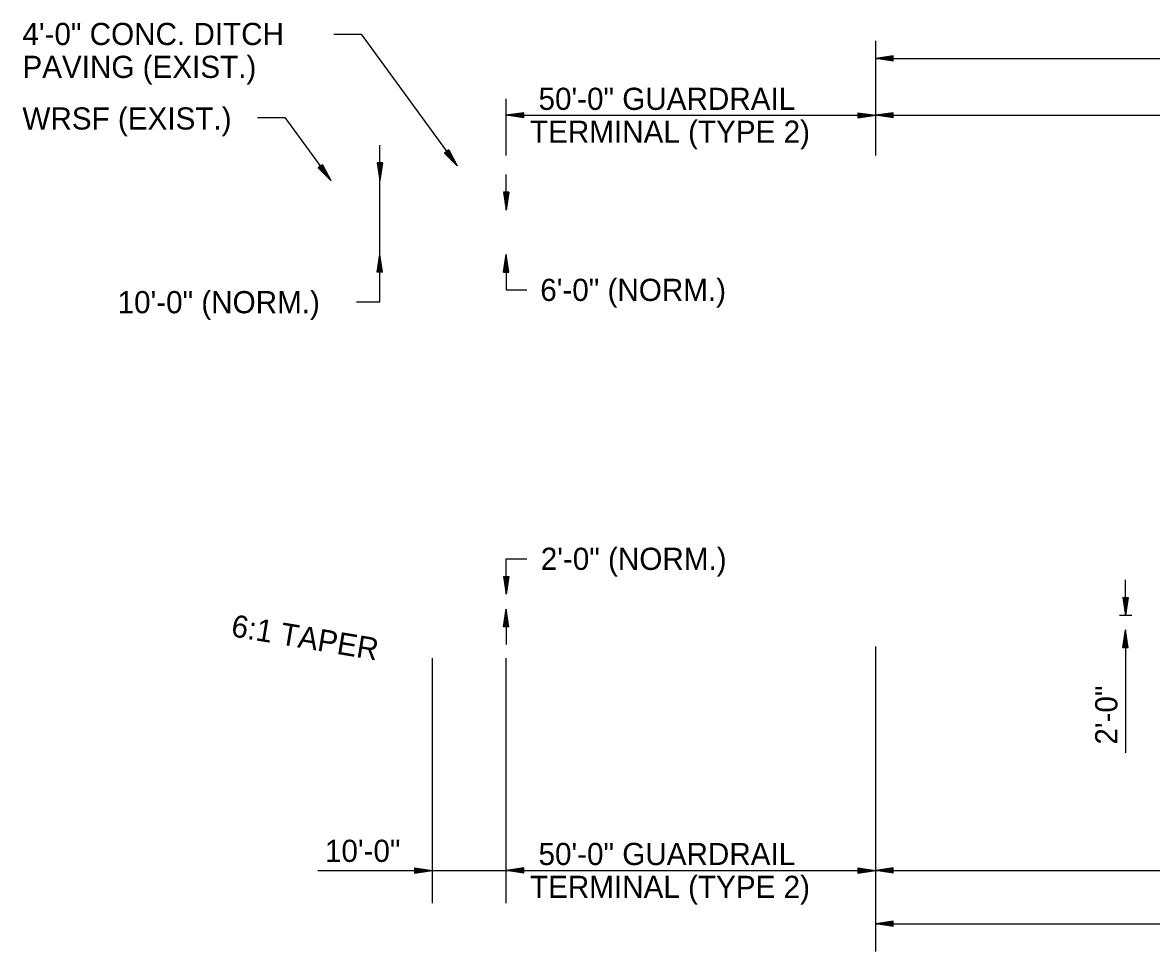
# Model space of a CAD drawing. Extents: x 1373853 to 1374003, y 380191 to 380927.
# Drawn here: x 1373853.14 to 1373883.7, y 380209.17 to 380234.32 of the extents above; entities that cross this region are included whole.
import ezdxf

# ---------------------------------------------------------------- set-up
doc = ezdxf.new("R2010")
doc.units = 0
doc.layers.add('2', color=7, linetype='Continuous')
doc.layers.add('7', color=7, linetype='Continuous')

msp = doc.modelspace()

# ---------------------------------------------------------------- linework, layer by layer
at = {"layer": '2'}
for p, q in [((1373876.236, 380230.714), (1373876.236, 380233.821)), ((1373876.236, 380233.341), (1373916.236, 380233.341)), ((1373866.236, 380230.714), (1373866.236, 380232.252)), ((1373866.236, 380231.806), (1373876.236, 380231.806)), ((1373876.236, 380231.806), (1373916.236, 380231.806)), ((1373862.817, 380230.041), (1373862.817, 380230.997)), ((1373866.236, 380229.241), (1373866.236, 380230.201)), ((1373862.817, 380228.041), (1373862.817, 380230.041)), ((1373862.817, 380226.748), (1373862.817, 380228.041)), ((1373862.817, 380226.748), (1373862.18, 380226.748)), ((1373882.998, 380218.276), (1373882.996, 380219.236)), ((1373866.236, 380218.441), (1373866.236, 380217.481)), ((1373882.831, 380218.276), (1373883.166, 380218.276)), ((1373882.998, 380217.876), (1373882.998, 380214.551)), ((1373876.236, 380209.174), (1373876.236, 380217.429)), ((1373864.236, 380210.478), (1373864.236, 380217.114)), ((1373866.236, 380210.478), (1373866.236, 380217.114)), ((1373861.131, 380211.366), (1373864.236, 380211.366)), ((1373864.236, 380211.366), (1373866.236, 380211.366)), ((1373866.236, 380211.366), (1373876.236, 380211.366)), ((1373876.236, 380211.366), (1373916.236, 380211.366)), ((1373876.236, 380209.921), (1373916.236, 380209.921))]:
    msp.add_line(p, q, dxfattribs=at)
for points in [[(1373861.572, 380234.001), (1373862.31, 380234.001), (1373864.903, 380230.441)], [(1373859.505, 380231.744), (1373860.243, 380231.744), (1373861.483, 380230.041)], [(1373866.236, 380228.041), (1373866.233, 380227.081), (1373866.792, 380227.081)], [(1373866.236, 380218.841), (1373866.233, 380219.801), (1373866.792, 380219.801)]]:
    msp.add_lwpolyline(points, dxfattribs=at)
at = {"layer": '7'}
for p, q in [((1373876.713, 380233.412), (1373876.236, 380233.341)), ((1373876.713, 380233.269), (1373876.713, 380233.412)), ((1373876.713, 380233.269), (1373876.236, 380233.341)), ((1373876.713, 380233.4), (1373876.315, 380233.341)), ((1373876.713, 380233.281), (1373876.315, 380233.341)), ((1373876.713, 380233.388), (1373876.398, 380233.341)), ((1373876.713, 380233.293), (1373876.398, 380233.341)), ((1373876.713, 380233.376), (1373876.479, 380233.341)), ((1373876.713, 380233.305), (1373876.479, 380233.341)), ((1373876.713, 380233.364), (1373876.558, 380233.341)), ((1373876.713, 380233.317), (1373876.558, 380233.341)), ((1373876.713, 380233.35), (1373876.639, 380233.341)), ((1373876.713, 380233.329), (1373876.639, 380233.341)), ((1373866.713, 380231.877), (1373866.236, 380231.806)), ((1373866.713, 380231.734), (1373866.713, 380231.877)), ((1373875.756, 380231.877), (1373876.236, 380231.806)), ((1373875.756, 380231.877), (1373875.756, 380231.734)), ((1373876.713, 380231.877), (1373876.236, 380231.806)), ((1373876.713, 380231.734), (1373876.713, 380231.877)), ((1373866.713, 380231.734), (1373866.236, 380231.806)), ((1373866.713, 380231.865), (1373866.315, 380231.806)), ((1373866.713, 380231.746), (1373866.315, 380231.806)), ((1373866.713, 380231.853), (1373866.398, 380231.806)), ((1373866.713, 380231.758), (1373866.398, 380231.806)), ((1373866.713, 380231.841), (1373866.479, 380231.806)), ((1373866.713, 380231.77), (1373866.479, 380231.806)), ((1373866.713, 380231.829), (1373866.558, 380231.806)), ((1373866.713, 380231.782), (1373866.558, 380231.806)), ((1373866.713, 380231.815), (1373866.639, 380231.806)), ((1373866.713, 380231.794), (1373866.639, 380231.806)), ((1373875.756, 380231.865), (1373876.155, 380231.806)), ((1373875.756, 380231.853), (1373876.071, 380231.806)), ((1373875.756, 380231.841), (1373875.992, 380231.806)), ((1373875.756, 380231.829), (1373875.913, 380231.806)), ((1373875.756, 380231.818), (1373875.832, 380231.806)), ((1373875.756, 380231.734), (1373876.236, 380231.806)), ((1373875.756, 380231.782), (1373875.913, 380231.806)), ((1373875.756, 380231.758), (1373876.071, 380231.806)), ((1373875.756, 380231.746), (1373876.155, 380231.806)), ((1373875.756, 380231.77), (1373875.992, 380231.806)), ((1373875.756, 380231.794), (1373875.832, 380231.806)), ((1373876.713, 380231.734), (1373876.236, 380231.806)), ((1373876.713, 380231.865), (1373876.315, 380231.806)), ((1373876.713, 380231.746), (1373876.315, 380231.806)), ((1373876.713, 380231.853), (1373876.398, 380231.806)), ((1373876.713, 380231.758), (1373876.398, 380231.806)), ((1373876.713, 380231.841), (1373876.479, 380231.806)), ((1373876.713, 380231.77), (1373876.479, 380231.806)), ((1373876.713, 380231.829), (1373876.558, 380231.806)), ((1373876.713, 380231.782), (1373876.558, 380231.806)), ((1373876.713, 380231.815), (1373876.639, 380231.806)), ((1373876.713, 380231.794), (1373876.639, 380231.806)), ((1373864.68, 380230.869), (1373864.564, 380230.785)), ((1373864.564, 380230.785), (1373864.903, 380230.441)), ((1373864.574, 380230.792), (1373864.857, 380230.505)), ((1373864.583, 380230.799), (1373864.808, 380230.572)), ((1373864.593, 380230.806), (1373864.76, 380230.638)), ((1373864.603, 380230.813), (1373864.713, 380230.702)), ((1373864.614, 380230.822), (1373864.666, 380230.767)), ((1373864.632, 380230.834), (1373864.666, 380230.767)), ((1373864.641, 380230.841), (1373864.713, 380230.702)), ((1373864.651, 380230.848), (1373864.76, 380230.638)), ((1373864.661, 380230.855), (1373864.808, 380230.572)), ((1373864.67, 380230.862), (1373864.857, 380230.505)), ((1373864.68, 380230.869), (1373864.903, 380230.441)), ((1373861.26, 380230.469), (1373861.144, 380230.385)), ((1373861.144, 380230.385), (1373861.483, 380230.041)), ((1373861.154, 380230.392), (1373861.437, 380230.105)), ((1373861.164, 380230.399), (1373861.388, 380230.172)), ((1373861.173, 380230.406), (1373861.34, 380230.238)), ((1373861.183, 380230.413), (1373861.294, 380230.302)), ((1373861.194, 380230.422), (1373861.246, 380230.367)), ((1373861.212, 380230.434), (1373861.246, 380230.367)), ((1373861.221, 380230.441), (1373861.294, 380230.302)), ((1373861.231, 380230.448), (1373861.34, 380230.238)), ((1373861.241, 380230.455), (1373861.388, 380230.172)), ((1373861.25, 380230.462), (1373861.437, 380230.105)), ((1373861.26, 380230.469), (1373861.483, 380230.041)), ((1373862.745, 380230.519), (1373862.817, 380230.041)), ((1373862.888, 380230.519), (1373862.745, 380230.519)), ((1373862.757, 380230.519), (1373862.817, 380230.12)), ((1373862.769, 380230.519), (1373862.817, 380230.204)), ((1373862.781, 380230.519), (1373862.817, 380230.285)), ((1373862.792, 380230.519), (1373862.817, 380230.364)), ((1373862.807, 380230.519), (1373862.816, 380230.445)), ((1373862.828, 380230.519), (1373862.816, 380230.445)), ((1373862.888, 380230.519), (1373862.817, 380230.041)), ((1373862.84, 380230.519), (1373862.817, 380230.364)), ((1373862.864, 380230.519), (1373862.817, 380230.204)), ((1373862.876, 380230.519), (1373862.817, 380230.12)), ((1373862.852, 380230.519), (1373862.817, 380230.285)), ((1373866.164, 380229.721), (1373866.236, 380229.241)), ((1373866.307, 380229.721), (1373866.164, 380229.721)), ((1373866.176, 380229.721), (1373866.236, 380229.322)), ((1373866.188, 380229.721), (1373866.236, 380229.404)), ((1373866.2, 380229.721), (1373866.236, 380229.485)), ((1373866.212, 380229.721), (1373866.236, 380229.566)), ((1373866.224, 380229.721), (1373866.236, 380229.645)), ((1373866.307, 380229.721), (1373866.236, 380229.241)), ((1373866.26, 380229.721), (1373866.236, 380229.566)), ((1373866.284, 380229.721), (1373866.236, 380229.404)), ((1373866.296, 380229.721), (1373866.236, 380229.322)), ((1373866.272, 380229.721), (1373866.236, 380229.485)), ((1373866.248, 380229.721), (1373866.236, 380229.645)), ((1373862.745, 380227.564), (1373862.817, 380228.041)), ((1373862.757, 380227.564), (1373862.817, 380227.962)), ((1373862.888, 380227.563), (1373862.817, 380228.041)), ((1373862.876, 380227.563), (1373862.817, 380227.962)), ((1373866.162, 380227.561), (1373866.236, 380228.041)), ((1373866.176, 380227.561), (1373866.236, 380227.96)), ((1373866.307, 380227.561), (1373866.236, 380228.041)), ((1373866.296, 380227.561), (1373866.236, 380227.96)), ((1373862.769, 380227.564), (1373862.817, 380227.879)), ((1373862.781, 380227.564), (1373862.817, 380227.798)), ((1373862.792, 380227.564), (1373862.817, 380227.719)), ((1373862.807, 380227.563), (1373862.816, 380227.638)), ((1373862.828, 380227.563), (1373862.816, 380227.638)), ((1373862.864, 380227.563), (1373862.817, 380227.879)), ((1373862.852, 380227.563), (1373862.817, 380227.798)), ((1373862.84, 380227.563), (1373862.817, 380227.719)), ((1373866.188, 380227.561), (1373866.236, 380227.879)), ((1373866.2, 380227.561), (1373866.236, 380227.798)), ((1373866.212, 380227.561), (1373866.236, 380227.719)), ((1373866.224, 380227.561), (1373866.236, 380227.638)), ((1373866.281, 380227.561), (1373866.236, 380227.879)), ((1373866.272, 380227.561), (1373866.236, 380227.798)), ((1373866.257, 380227.561), (1373866.236, 380227.719)), ((1373866.245, 380227.561), (1373866.236, 380227.638)), ((1373862.888, 380227.563), (1373862.745, 380227.564)), ((1373866.162, 380227.561), (1373866.307, 380227.561)), ((1373866.162, 380219.321), (1373866.236, 380218.841)), ((1373866.162, 380219.321), (1373866.307, 380219.321)), ((1373866.176, 380219.321), (1373866.236, 380218.922)), ((1373866.188, 380219.321), (1373866.236, 380219.004)), ((1373866.2, 380219.321), (1373866.236, 380219.085)), ((1373866.212, 380219.321), (1373866.236, 380219.164)), ((1373866.224, 380219.321), (1373866.236, 380219.245)), ((1373866.307, 380219.321), (1373866.236, 380218.841)), ((1373866.257, 380219.321), (1373866.236, 380219.164)), ((1373866.281, 380219.321), (1373866.236, 380219.004)), ((1373866.296, 380219.321), (1373866.236, 380218.922)), ((1373866.272, 380219.321), (1373866.236, 380219.085)), ((1373866.245, 380219.321), (1373866.236, 380219.245)), ((1373882.924, 380218.756), (1373882.998, 380218.276)), ((1373882.924, 380218.756), (1373883.07, 380218.756)), ((1373882.939, 380218.756), (1373882.998, 380218.357)), ((1373882.951, 380218.756), (1373882.998, 380218.438)), ((1373882.963, 380218.756), (1373882.998, 380218.52)), ((1373882.975, 380218.756), (1373882.998, 380218.598)), ((1373882.986, 380218.756), (1373882.998, 380218.68)), ((1373883.07, 380218.756), (1373882.998, 380218.276)), ((1373883.02, 380218.756), (1373882.998, 380218.598)), ((1373883.044, 380218.756), (1373882.998, 380218.438)), ((1373883.058, 380218.756), (1373882.998, 380218.357)), ((1373883.034, 380218.756), (1373882.998, 380218.52)), ((1373883.008, 380218.756), (1373882.998, 380218.68)), ((1373866.164, 380217.961), (1373866.236, 380218.441)), ((1373866.307, 380217.961), (1373866.236, 380218.441)), ((1373866.176, 380217.961), (1373866.236, 380218.36)), ((1373866.188, 380217.961), (1373866.236, 380218.279)), ((1373866.2, 380217.961), (1373866.236, 380218.198)), ((1373866.296, 380217.961), (1373866.236, 380218.36)), ((1373866.284, 380217.961), (1373866.236, 380218.279)), ((1373866.272, 380217.961), (1373866.236, 380218.198)), ((1373866.307, 380217.961), (1373866.164, 380217.961)), ((1373866.212, 380217.961), (1373866.236, 380218.116)), ((1373866.224, 380217.961), (1373866.236, 380218.038)), ((1373866.26, 380217.961), (1373866.236, 380218.116)), ((1373866.248, 380217.961), (1373866.236, 380218.038)), ((1373882.927, 380217.396), (1373882.998, 380217.876)), ((1373883.07, 380217.396), (1373882.998, 380217.876)), ((1373882.939, 380217.396), (1373882.998, 380217.795)), ((1373882.951, 380217.396), (1373882.998, 380217.714)), ((1373882.963, 380217.396), (1373882.998, 380217.632)), ((1373882.975, 380217.396), (1373882.998, 380217.551)), ((1373883.058, 380217.396), (1373882.998, 380217.795)), ((1373883.046, 380217.396), (1373882.998, 380217.714)), ((1373883.034, 380217.396), (1373882.998, 380217.632)), ((1373883.022, 380217.396), (1373882.998, 380217.551)), ((1373883.07, 380217.396), (1373882.927, 380217.396)), ((1373882.986, 380217.396), (1373882.998, 380217.472)), ((1373883.01, 380217.396), (1373882.998, 380217.472)), ((1373863.756, 380211.437), (1373864.236, 380211.366)), ((1373863.756, 380211.437), (1373863.756, 380211.294)), ((1373863.756, 380211.425), (1373864.155, 380211.366)), ((1373863.756, 380211.413), (1373864.071, 380211.366)), ((1373866.713, 380211.437), (1373866.236, 380211.366)), ((1373866.713, 380211.425), (1373866.315, 380211.366)), ((1373866.713, 380211.413), (1373866.398, 380211.366)), ((1373866.713, 380211.294), (1373866.713, 380211.437)), ((1373875.756, 380211.437), (1373876.236, 380211.366)), ((1373875.756, 380211.437), (1373875.756, 380211.294)), ((1373875.756, 380211.425), (1373876.155, 380211.366)), ((1373875.756, 380211.413), (1373876.071, 380211.366)), ((1373876.713, 380211.437), (1373876.236, 380211.366)), ((1373876.713, 380211.425), (1373876.315, 380211.366)), ((1373876.713, 380211.413), (1373876.398, 380211.366)), ((1373876.713, 380211.294), (1373876.713, 380211.437)), ((1373863.756, 380211.401), (1373863.992, 380211.366)), ((1373863.756, 380211.39), (1373863.913, 380211.366)), ((1373863.756, 380211.378), (1373863.832, 380211.366)), ((1373863.756, 380211.294), (1373864.236, 380211.366)), ((1373863.756, 380211.342), (1373863.913, 380211.366)), ((1373863.756, 380211.318), (1373864.071, 380211.366)), ((1373863.756, 380211.306), (1373864.155, 380211.366)), ((1373863.756, 380211.33), (1373863.992, 380211.366)), ((1373863.756, 380211.354), (1373863.832, 380211.366)), ((1373866.713, 380211.294), (1373866.236, 380211.366)), ((1373866.713, 380211.306), (1373866.315, 380211.366)), ((1373866.713, 380211.318), (1373866.398, 380211.366)), ((1373866.713, 380211.401), (1373866.479, 380211.366)), ((1373866.713, 380211.33), (1373866.479, 380211.366)), ((1373866.713, 380211.39), (1373866.558, 380211.366)), ((1373866.713, 380211.342), (1373866.558, 380211.366)), ((1373866.713, 380211.375), (1373866.639, 380211.366)), ((1373866.713, 380211.354), (1373866.639, 380211.366)), ((1373875.756, 380211.401), (1373875.992, 380211.366)), ((1373875.756, 380211.39), (1373875.913, 380211.366)), ((1373875.756, 380211.378), (1373875.832, 380211.366)), ((1373875.756, 380211.294), (1373876.236, 380211.366)), ((1373875.756, 380211.342), (1373875.913, 380211.366)), ((1373875.756, 380211.318), (1373876.071, 380211.366)), ((1373875.756, 380211.306), (1373876.155, 380211.366)), ((1373875.756, 380211.33), (1373875.992, 380211.366)), ((1373875.756, 380211.354), (1373875.832, 380211.366)), ((1373876.713, 380211.294), (1373876.236, 380211.366)), ((1373876.713, 380211.306), (1373876.315, 380211.366)), ((1373876.713, 380211.318), (1373876.398, 380211.366)), ((1373876.713, 380211.401), (1373876.479, 380211.366)), ((1373876.713, 380211.33), (1373876.479, 380211.366)), ((1373876.713, 380211.39), (1373876.558, 380211.366)), ((1373876.713, 380211.342), (1373876.558, 380211.366)), ((1373876.713, 380211.375), (1373876.639, 380211.366)), ((1373876.713, 380211.354), (1373876.639, 380211.366)), ((1373876.713, 380209.993), (1373876.236, 380209.921)), ((1373876.713, 380209.849), (1373876.236, 380209.921)), ((1373876.713, 380209.981), (1373876.315, 380209.921)), ((1373876.713, 380209.861), (1373876.315, 380209.921)), ((1373876.713, 380209.969), (1373876.398, 380209.921)), ((1373876.713, 380209.873), (1373876.398, 380209.921)), ((1373876.713, 380209.957), (1373876.479, 380209.921)), ((1373876.713, 380209.885), (1373876.479, 380209.921)), ((1373876.713, 380209.945), (1373876.558, 380209.921)), ((1373876.713, 380209.897), (1373876.558, 380209.921)), ((1373876.713, 380209.931), (1373876.639, 380209.921)), ((1373876.713, 380209.909), (1373876.639, 380209.921)), ((1373876.713, 380209.849), (1373876.713, 380209.993))]:
    msp.add_line(p, q, dxfattribs=at)

# ---------------------------------------------------------------- texts
at = {"layer": '2'}
for s, p in [('4\'-0" CONC. DITCH', (1373853.139, 380233.707)), ('PAVING (EXIST.)', (1373853.139, 380232.817)), ('WRSF (EXIST.)', (1373853.139, 380231.42)), ('10\'-0" (NORM.)', (1373855.715, 380226.448))]:
    msp.add_text(s, height=0.6, dxfattribs=at).set_placement(p)
for s, rotation, p in [('50\'-0" GUARDRAIL', 0, (1373867.109, 380231.952)), ('TERMINAL (TYPE 2)', 0, (1373866.878, 380231.062)), ('6\'-0" (NORM.)', 0, (1373867.156, 380226.781)), ('2\'-0" (NORM.)', 360, (1373867.17, 380219.501)), ('6:1 TAPER', 350.5377, (1373858.764, 380217.708)), ('2\'-0"', 90, (1373882.777, 380214.772)), ('10\'-0"', 0, (1373861.328, 380211.597)), ('50\'-0" GUARDRAIL', 0, (1373867.109, 380211.512)), ('TERMINAL (TYPE 2)', 0, (1373866.878, 380210.622))]:
    msp.add_text(s, height=0.6, rotation=rotation, dxfattribs=at).set_placement(p)

doc.saveas('drawing.dxf')
